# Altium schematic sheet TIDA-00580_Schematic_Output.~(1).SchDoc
size 431 x 279 mm; Date: Not shown in title block; ApprovedBy: Not shown in title block; CheckedBy: Not shown in title block; Author: Not shown in title block; CompanyName: Not shown in title block; Engineer: Not shown in title block; Organization: Not shown in title block; Address1: Not shown in title block; Address2: Not shown in title block; Address3: Not shown in title block; Address4: Not shown in title block; DocumentNumber: 1; Revision: Use project parameter SCH_Rev; SheetNumber: 2; SheetTotal: 3; PageSetup: Record=PageOptions¦CenterHorizontal=True¦CenterVertical=True¦PrintScale=1.00¦XCorrection=1.00¦YCorrection=1.00¦PrintKind=0¦BorderSize=5000000¦LeftOffset=0¦BottomOffset=0¦Orientation=2¦PaperLength=1000¦PaperWidth=1000¦Scale=100¦PaperSource=15¦PrintQuality=600¦MediaType=1¦DitherType=10¦PaperKind=Letter¦PrintScaleMode=1
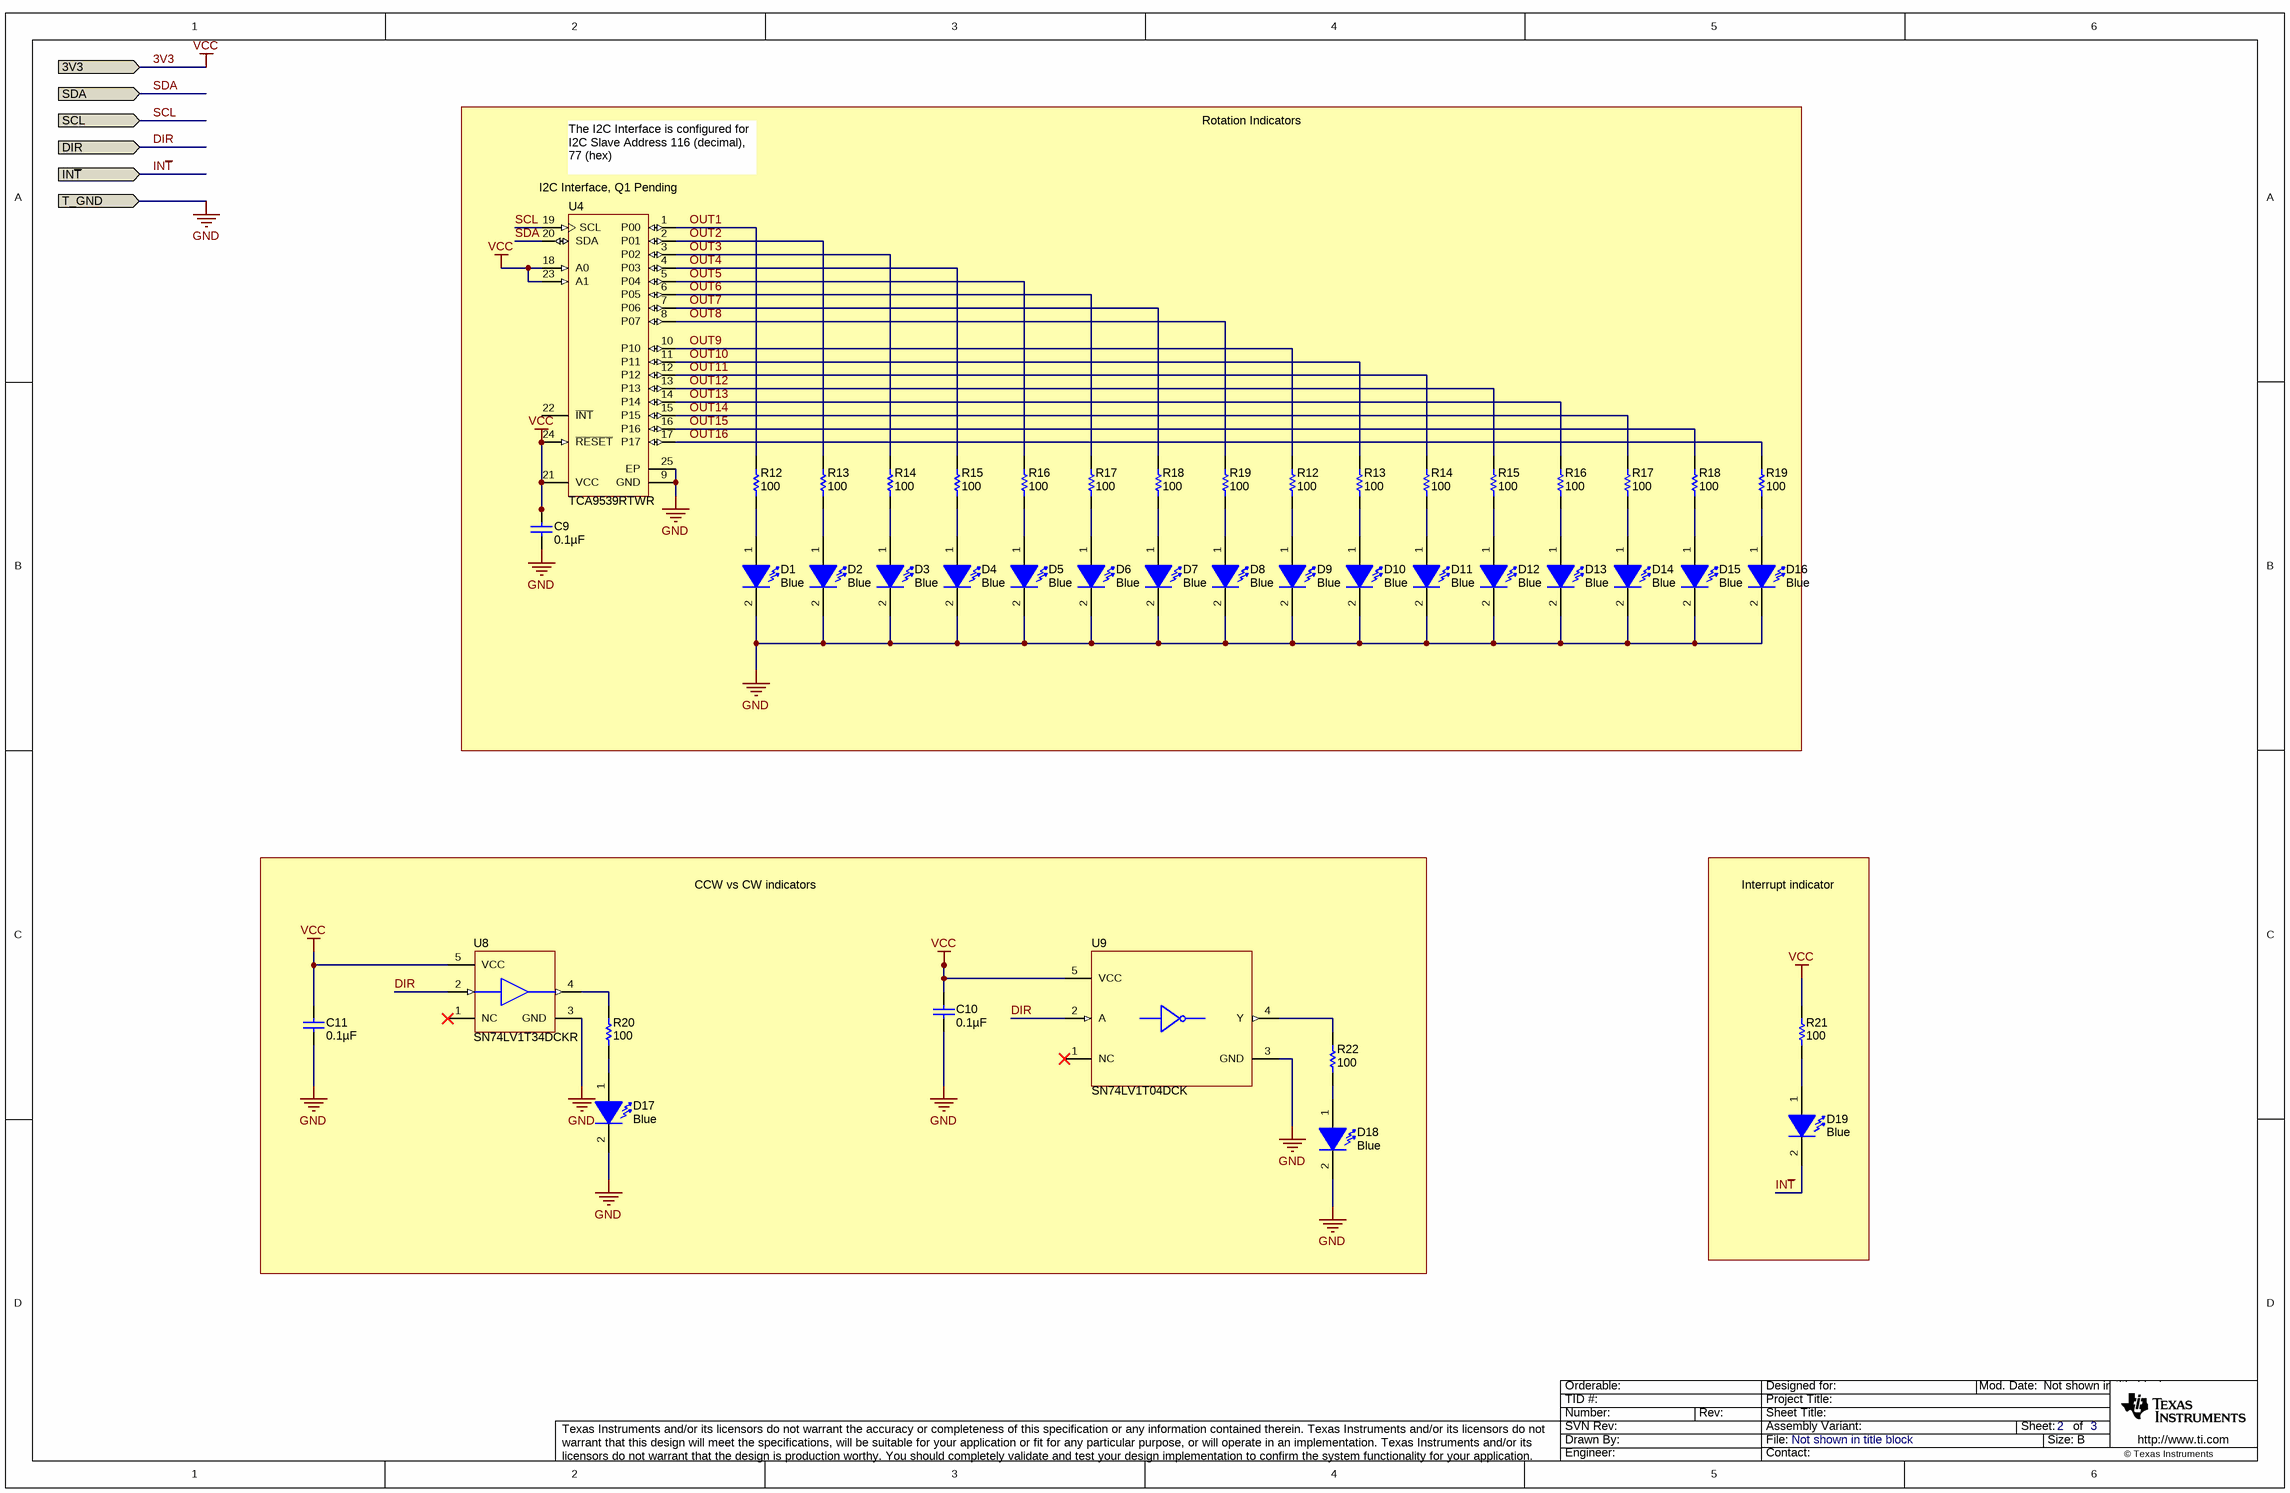
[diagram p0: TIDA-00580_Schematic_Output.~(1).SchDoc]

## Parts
(Parts that share a designator on the sheet are numbered #1, #2 ... from top to bottom, then left to right.)
C9  ValueDisplayed: 0.1µF  [0603]  (hidden comment: 0603YC104JAT2A)
C10  ValueDisplayed: 0.1µF  [0603]  (hidden comment: 0603YC104JAT2A)
C11  ValueDisplayed: 0.1µF  [0603]  (hidden comment: 0603YC104JAT2A)
D1  value Blue  [LB Q39G_BLUE]  (hidden comment: LB Q39G-L2N2-35-1)
D2  value Blue  [LB Q39G_BLUE]  (hidden comment: LB Q39G-L2N2-35-1)
D3  value Blue  [LB Q39G_BLUE]  (hidden comment: LB Q39G-L2N2-35-1)
D4  value Blue  [LB Q39G_BLUE]  (hidden comment: LB Q39G-L2N2-35-1)
D5  value Blue  [LB Q39G_BLUE]  (hidden comment: LB Q39G-L2N2-35-1)
D6  value Blue  [LB Q39G_BLUE]  (hidden comment: LB Q39G-L2N2-35-1)
D7  value Blue  [LB Q39G_BLUE]  (hidden comment: LB Q39G-L2N2-35-1)
D8  value Blue  [LB Q39G_BLUE]  (hidden comment: LB Q39G-L2N2-35-1)
D9  value Blue  [LB Q39G_BLUE]  (hidden comment: LB Q39G-L2N2-35-1)
D10  value Blue  [LB Q39G_BLUE]  (hidden comment: LB Q39G-L2N2-35-1)
D11  value Blue  [LB Q39G_BLUE]  (hidden comment: LB Q39G-L2N2-35-1)
D12  value Blue  [LB Q39G_BLUE]  (hidden comment: LB Q39G-L2N2-35-1)
D13  value Blue  [LB Q39G_BLUE]  (hidden comment: LB Q39G-L2N2-35-1)
D14  value Blue  [LB Q39G_BLUE]  (hidden comment: LB Q39G-L2N2-35-1)
D15  value Blue  [LB Q39G_BLUE]  (hidden comment: LB Q39G-L2N2-35-1)
D16  value Blue  [LB Q39G_BLUE]  (hidden comment: LB Q39G-L2N2-35-1)
D17  value Blue  [LB Q39G_BLUE]  (hidden comment: LB Q39G-L2N2-35-1)
D18  value Blue  [LB Q39G_BLUE]  (hidden comment: LB Q39G-L2N2-35-1)
D19  value Blue  [LB Q39G_BLUE]  (hidden comment: LB Q39G-L2N2-35-1)
R12#1  ValueDisplayed: 100  [0603]  (hidden comment: CRCW0603100RJNEA)
R12#2  ValueDisplayed: 100  [0603]  (hidden comment: CRCW0603100RJNEA)
R13#1  ValueDisplayed: 100  [0603]  (hidden comment: CRCW0603100RJNEA)
R13#2  ValueDisplayed: 100  [0603]  (hidden comment: CRCW0603100RJNEA)
R14#1  ValueDisplayed: 100  [0603]  (hidden comment: CRCW0603100RJNEA)
R14#2  ValueDisplayed: 100  [0603]  (hidden comment: CRCW0603100RJNEA)
R15#1  ValueDisplayed: 100  [0603]  (hidden comment: CRCW0603100RJNEA)
R15#2  ValueDisplayed: 100  [0603]  (hidden comment: CRCW0603100RJNEA)
R16#1  ValueDisplayed: 100  [0603]  (hidden comment: CRCW0603100RJNEA)
R16#2  ValueDisplayed: 100  [0603]  (hidden comment: CRCW0603100RJNEA)
R17#1  ValueDisplayed: 100  [0603]  (hidden comment: CRCW0603100RJNEA)
R17#2  ValueDisplayed: 100  [0603]  (hidden comment: CRCW0603100RJNEA)
R18#1  ValueDisplayed: 100  [0603]  (hidden comment: CRCW0603100RJNEA)
R18#2  ValueDisplayed: 100  [0603]  (hidden comment: CRCW0603100RJNEA)
R19#1  ValueDisplayed: 100  [0603]  (hidden comment: CRCW0603100RJNEA)
R19#2  ValueDisplayed: 100  [0603]  (hidden comment: CRCW0603100RJNEA)
R20  ValueDisplayed: 100  [0603]  (hidden comment: CRCW0603100RJNEA)
R21  ValueDisplayed: 100  [0603]  (hidden comment: CRCW0603100RJNEA)
R22  ValueDisplayed: 100  [0603]  (hidden comment: CRCW0603100RJNEA)
U4  TCA9539RTWR  [RTW0024B]
U8  SN74LV1T34DCKR  [DCK0005A_N]
U9  SN74LV1T04DCK  [DCK0005A_N]

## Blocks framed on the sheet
CCW vs CW indicators: C10 C11 D17 D18 R20 R22 U8 U9
Interrupt indicator: D19 R21

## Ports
3V3 (in), DIR (in), IN~{T} (in), SCL (in), SDA (in), T_GND (in)

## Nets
3V3: C9.1 C10.1 C11.1 R21.2 U4.18(A0) U4.21(VCC) U4.23(A1) U4.24(~{RESET}) U8.5(VCC) U9.5(VCC) ; port 3V3  [also labelled VCC]
GND: C9.2 C10.2 C11.2 D1.2(K) D2.2(K) D3.2(K) D4.2(K) D5.2(K) D6.2(K) D7.2(K) D8.2(K) D9.2(K) D10.2(K) D11.2(K) D12.2(K) D13.2(K) D14.2(K) D15.2(K) D16.2(K) D17.2(K) D18.2(K) U4.9(GND) U4.25(EP) U8.3(GND) U9.3(GND) ; port T_GND
IN~{T}: D19.2(K) ; port IN~{T}
DIR: U8.2(A) U9.2(A) ; port DIR
OUT1: R12#1.2 U4.1(P00)
OUT2: R13#1.2 U4.2(P01)
OUT3: R14#1.2 U4.3(P02)
OUT4: R15#1.2 U4.4(P03)
OUT5: R16#1.2 U4.5(P04)
OUT6: R17#1.2 U4.6(P05)
OUT7: R18#1.2 U4.7(P06)
OUT8: R19#1.2 U4.8(P07)
OUT9: R12#2.2 U4.10(P10)
OUT10: R13#2.2 U4.11(P11)
OUT11: R14#2.2 U4.12(P12)
OUT12: R15#2.2 U4.13(P13)
OUT13: R16#2.2 U4.14(P14)
OUT14: R17#2.2 U4.15(P15)
OUT15: R18#2.2 U4.16(P16)
OUT16: R19#2.2 U4.17(P17)
SCL: U4.19(SCL) ; port SCL
SDA: U4.20(SDA) ; port SDA
NetD1_1: D1.1(A) R12#1.1
NetD2_1: D2.1(A) R13#1.1
NetD3_1: D3.1(A) R14#1.1
NetD4_1: D4.1(A) R15#1.1
NetD5_1: D5.1(A) R16#1.1
NetD6_1: D6.1(A) R17#1.1
NetD7_1: D7.1(A) R18#1.1
NetD8_1: D8.1(A) R19#1.1
NetD9_1: D9.1(A) R12#2.1
NetD10_1: D10.1(A) R13#2.1
NetD11_1: D11.1(A) R14#2.1
NetD12_1: D12.1(A) R15#2.1
NetD13_1: D13.1(A) R16#2.1
NetD14_1: D14.1(A) R17#2.1
NetD15_1: D15.1(A) R18#2.1
NetD16_1: D16.1(A) R19#2.1
NetD17_1: D17.1(A) R20.1
NetD18_1: D18.1(A) R22.1
NetD19_1: D19.1(A) R21.1
NetR20_2: R20.2 U8.4(Y)
NetR22_2: R22.2 U9.4(Y)

Not connected (* = marked no-connect by the designer): U4 22(~{INT}); U8 1(NC)*; U9 1(NC)*

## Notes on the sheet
- The I2C Interface is configured for I2C Slave Address 116 (decimal), 77 (hex)
- Rotation Indicators
- (near U4) I2C Interface, Q1 Pending

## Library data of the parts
C9-C11 = 0603YC104JAT2A: CAP, CERM, 0.1 µF, 16 V, +/- 5%, X7R, 0603; Manufacturer: AVX; Polarized: N; CompType: Capacitor; Value: 0.1uF; U/M: EA; Cap_F: 0.0000001; Tolerance_%: 5; ESR_ohm: 0.039; Value1: 0.039 ohm; VDC_V: 16; Value2: 16V; TaMin_C: -55; TaMax_C: 125
D1-D19 = LB Q39G-L2N2-35-1: LED, Blue, SMD; Manufacturer: OSRAM; Vf_V: 2.85; Value2: 2.85V; Io_A: 0.15; Tjmax_C: 95; Value1: W; U/M: EA
R12#1 R12#2 R13#1 R13#2 R14#1 R14#2 R15#1 R15#2 R16#1 R16#2 R17#1 R17#2 R18#1 R18#2 R19#1 R19#2 R20-R22 = CRCW0603100RJNEA: RES, 100, 5%, 0.1 W, 0603; Manufacturer: Vishay-Dale; CompType: Resistor; Value: 100; Value_Code: 100R; Tolerance_%: 5; Power_W: 0.1; Value2: 0.1W; VDC_V: 75; TempCo: 200 ppm/C; EIA_Code: E24; U/M: EA
U4 = TCA9539RTWR: Remote 16-Bit I2C and SMBus, Low-Power I/O Expander with Interrupt Output, Reset & Config. Register, 1.65 to 5.5 V, -40 to 85 degC, 24-pin QFN (RTW), Green (RoHS & no Sb/Br); Manufacturer: Texas Instruments; Alternate Manufacturer: None; Alternate PartNumber: Equivalent; SubFamily: I2C IO Expander; Interrupt Output: Yes; Max Frequency(kHz): 400; I2C Address: 1110 1xx; # of I/Os: 16
U8 = SN74LV1T34DCKR: Single Power Supply Single Buffer GATE CMOS Logic Level Shifter, DCK0005A; Manufacturer: Texas Instruments; SymbolCreator: Altium; CompType: IC; U/M: EA
U9 = SN74LV1T04DCK: SN74LV1T04 Single Power Supply Inverter Gate CMOS Logic Level Shifter, DCK0005A; Manufacturer: Texas Instruments; SymbolCreator: a0411947; CompType: IC; U/M: EA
